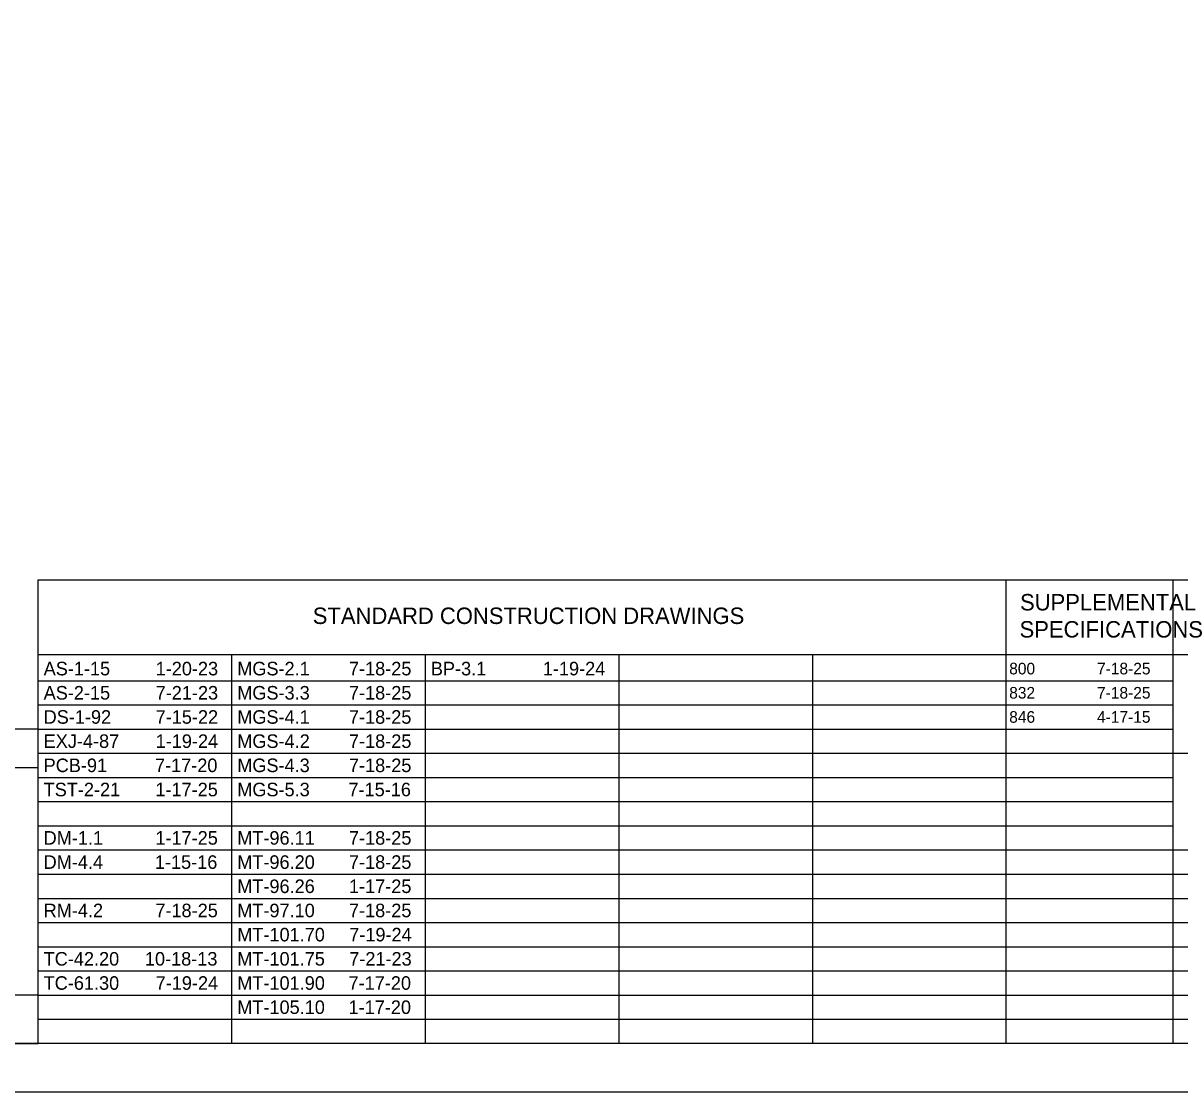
# Model space of a CAD drawing. Extents: x 6.3 to 40.3, y 9 to 31.
# Drawn here: x 16.34 to 28.29, y 9.05 to 20.09 of the extents above; entities that cross this region are included whole.
import ezdxf

# ---------------------------------------------------------------- set-up
doc = ezdxf.new("R2010")
doc.units = 0
for name, color, linetype in [('SH_Border', 7, 'Continuous'), ('SH_Cut_Line', 7, 'Continuous'), ('SH_Data', 7, 'Continuous'), ('SH_Text', 7, 'Continuous')]:
    doc.layers.add(name, color=color, linetype=linetype)

msp = doc.modelspace()

# ---------------------------------------------------------------- linework, layer by layer
at = {"layer": 'SH_Border'}
msp.add_lwpolyline([(7.845, 30.546), (39.845, 30.546), (39.845, 9.546), (7.845, 9.546)], close=True, dxfattribs=at)
at = {"layer": 'SH_Cut_Line'}
msp.add_lwpolyline([(6.345, 9.046), (40.345, 9.046), (40.345, 31.046), (6.345, 31.046)], close=True, dxfattribs=at)
at = {"layer": 'SH_Data'}
for p, q in [((16.495, 14.337), (29.945, 14.337)), ((16.495, 9.546), (16.495, 14.337)), ((26.495, 9.546), (26.495, 14.337)), ((28.22, 9.546), (28.22, 14.337)), ((16.495, 13.567), (29.945, 13.567)), ((18.495, 9.546), (18.495, 13.567)), ((20.495, 9.546), (20.495, 13.567)), ((22.495, 9.546), (22.495, 13.567)), ((24.495, 9.546), (24.495, 13.567)), ((16.495, 13.296), (28.22, 13.296)), ((16.495, 13.046), (28.22, 13.046)), ((16.495, 12.796), (13.695, 12.796)), ((16.495, 12.796), (28.22, 12.796)), ((16.495, 9.546), (16.495, 12.796)), ((16.495, 12.546), (29.945, 12.546)), ((16.495, 12.396), (13.695, 12.396)), ((16.495, 12.296), (28.22, 12.296)), ((16.495, 12.046), (28.22, 12.046)), ((16.495, 11.796), (28.22, 11.796)), ((16.495, 11.546), (29.945, 11.546)), ((16.495, 11.296), (29.945, 11.296)), ((16.495, 11.046), (29.945, 11.046)), ((16.495, 10.796), (29.945, 10.796)), ((16.495, 10.546), (29.945, 10.546)), ((16.495, 10.296), (29.945, 10.296)), ((16.495, 10.046), (29.945, 10.046)), ((16.495, 9.796), (29.945, 9.796)), ((16.495, 9.546), (13.695, 9.546))]:
    msp.add_line(p, q, dxfattribs=at)
msp.add_lwpolyline([(16.495, 9.546), (16.495, 10.046), (13.695, 10.046), (13.695, 9.546)], close=True, dxfattribs=at)

# ---------------------------------------------------------------- texts
at = {"layer": 'SH_Text'}
for s, height, p in [('SUPPLEMENTAL', 0.17, (26.637, 14.022)), ('STANDARD CONSTRUCTION DRAWINGS', 0.17, (19.33, 13.882)), ('SPECIFICATIONS', 0.17, (26.632, 13.742)), ('AS-1-15', 0.14, (16.55, 13.351)), ('1-20-23', 0.14, (17.707, 13.351)), ('MGS-2.1', 0.14, (18.55, 13.351)), ('7-18-25', 0.14, (19.704, 13.351)), ('BP-3.1', 0.14, (20.55, 13.351)), ('1-19-24', 0.14, (21.707, 13.351)), ('800', 0.12, (26.525, 13.361)), ('7-18-25', 0.12, (27.432, 13.361)), ('AS-2-15', 0.14, (16.55, 13.101)), ('7-21-23', 0.14, (17.707, 13.101)), ('MGS-3.3', 0.14, (18.55, 13.101)), ('7-18-25', 0.14, (19.704, 13.101)), ('832', 0.12, (26.525, 13.111)), ('7-18-25', 0.12, (27.432, 13.111)), ('DS-1-92', 0.14, (16.55, 12.851)), ('7-15-22', 0.14, (17.707, 12.851)), ('MGS-4.1', 0.14, (18.55, 12.851)), ('7-18-25', 0.14, (19.704, 12.851)), ('846', 0.12, (26.525, 12.861)), ('4-17-15', 0.12, (27.432, 12.861)), ('EXJ-4-87', 0.14, (16.55, 12.601)), ('1-19-24', 0.14, (17.707, 12.601)), ('MGS-4.2', 0.14, (18.55, 12.601)), ('7-18-25', 0.14, (19.704, 12.601)), ('PCB-91', 0.14, (16.55, 12.351)), ('7-17-20', 0.14, (17.7, 12.351)), ('MGS-4.3', 0.14, (18.55, 12.351)), ('7-18-25', 0.14, (19.704, 12.351)), ('TST-2-21', 0.14, (16.55, 12.101)), ('1-17-25', 0.14, (17.704, 12.101)), ('MGS-5.3', 0.14, (18.55, 12.101)), ('7-15-16', 0.14, (19.699, 12.101)), ('DM-1.1', 0.14, (16.55, 11.601)), ('1-17-25', 0.14, (17.704, 11.601)), ('MT-96.11', 0.14, (18.55, 11.601)), ('7-18-25', 0.14, (19.704, 11.601)), ('DM-4.4', 0.14, (16.55, 11.351)), ('1-15-16', 0.14, (17.699, 11.351)), ('MT-96.20', 0.14, (18.55, 11.351)), ('7-18-25', 0.14, (19.704, 11.351)), ('MT-96.26', 0.14, (18.55, 11.101)), ('1-17-25', 0.14, (19.704, 11.101)), ('RM-4.2', 0.14, (16.55, 10.851)), ('7-18-25', 0.14, (17.704, 10.851)), ('MT-97.10', 0.14, (18.55, 10.851)), ('7-18-25', 0.14, (19.704, 10.851)), ('MT-101.70', 0.14, (18.55, 10.601)), ('7-19-24', 0.14, (19.707, 10.601)), ('TC-42.20', 0.14, (16.55, 10.351)), ('10-18-13', 0.14, (17.596, 10.351)), ('MT-101.75', 0.14, (18.55, 10.351)), ('7-21-23', 0.14, (19.707, 10.351)), ('TC-61.30', 0.14, (16.55, 10.101)), ('7-19-24', 0.14, (17.707, 10.101)), ('MT-101.90', 0.14, (18.55, 10.101)), ('7-17-20', 0.14, (19.7, 10.101)), ('MT-105.10', 0.14, (18.55, 9.851)), ('1-17-20', 0.14, (19.7, 9.851))]:
    msp.add_text(s, height=height, dxfattribs=at).set_placement(p)

doc.saveas('drawing.dxf')
